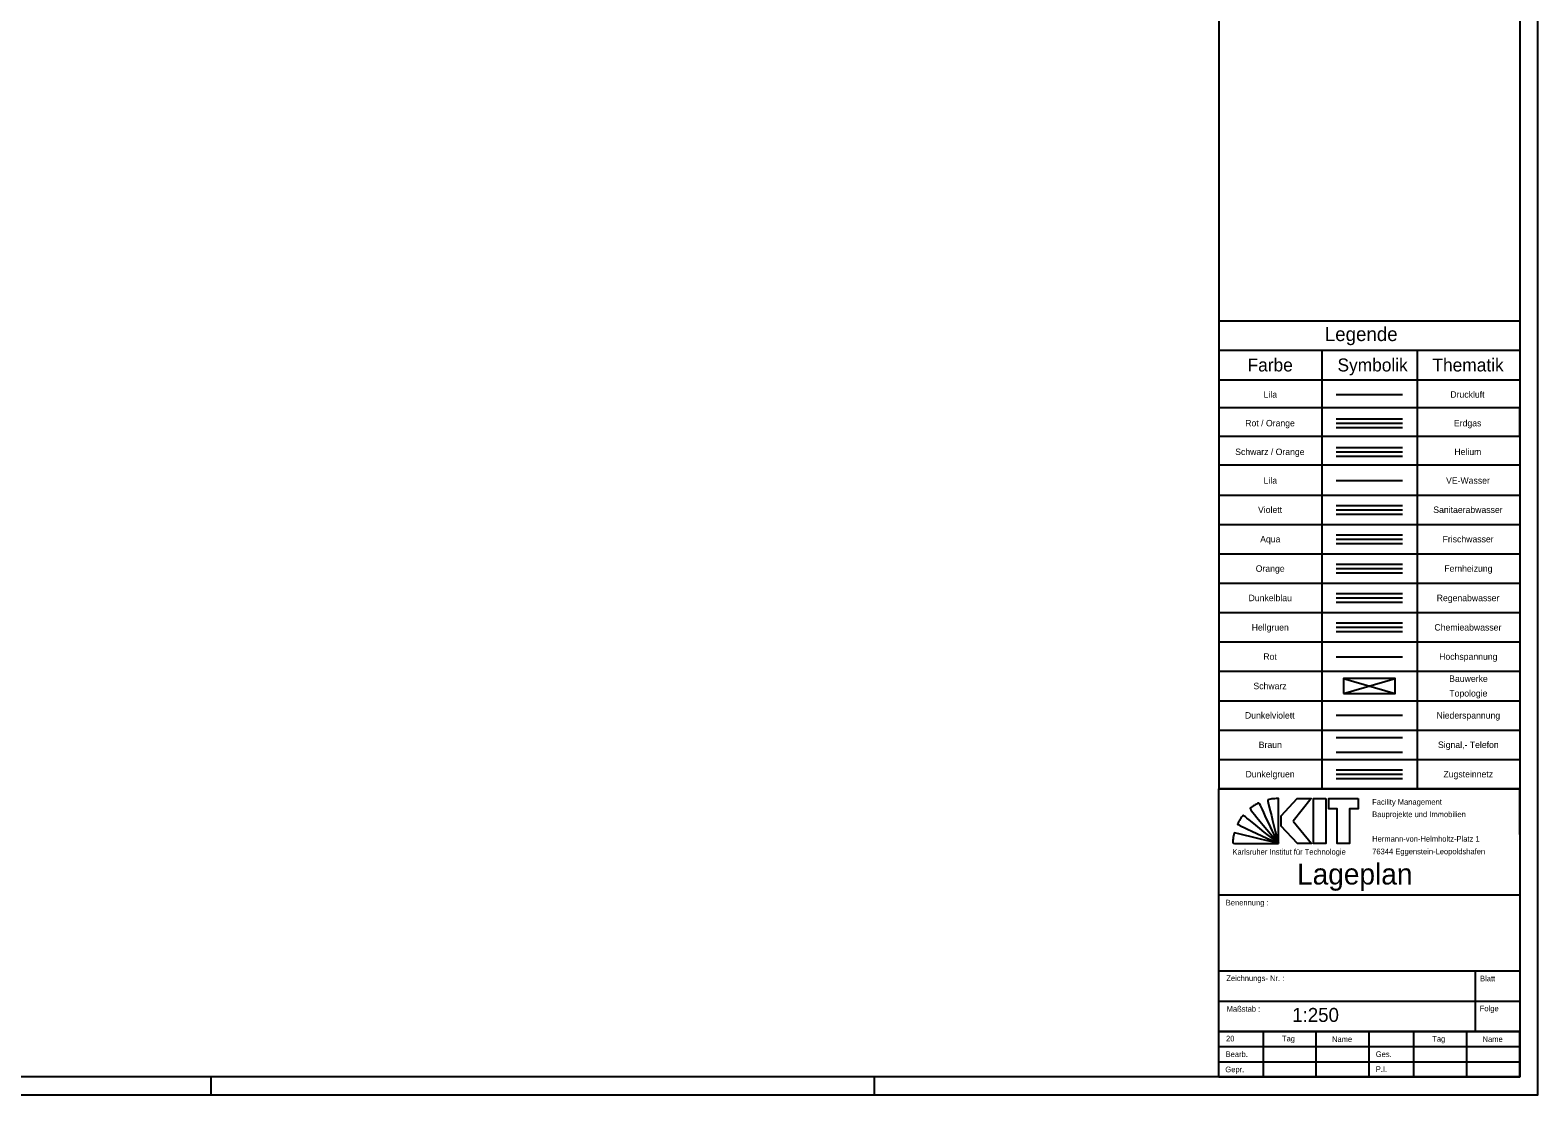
# Model space of a CAD drawing. Extents: x -36550144 to -36549934, y 4853173 to 4853322.
# Drawn here: x -36550038.7 to -36549933.6, y 4853173.1 to 4853247.4 of the extents above; entities that cross this region are included whole.
import ezdxf

# ---------------------------------------------------------------- set-up
doc = ezdxf.new("R2010")
doc.units = 0
doc.layers.add('Ebene 1', color=7, linetype='Continuous')

msp = doc.modelspace()

# ---------------------------------------------------------------- linework, layer by layer
at = {"layer": 'Ebene 1'}
for p, q in [((-36549934.81, 4853320.36), (-36549934.81, 4853219.03)), ((-36549955.81, 4853227.08), (-36549934.81, 4853227.08)), ((-36549934.81, 4853225.03), (-36549955.81, 4853225.03)), ((-36549948.63, 4853225.03), (-36549948.63, 4853194.46)), ((-36549941.98, 4853225.03), (-36549941.98, 4853194.46)), ((-36549955.81, 4853222.98), (-36549934.81, 4853222.98)), ((-36549947.61, 4853221.96), (-36549943, 4853221.96)), ((-36549934.81, 4853221.03), (-36549955.81, 4853221.03)), ((-36549934.81, 4853219.03), (-36549934.81, 4853221.08)), ((-36549947.61, 4853219.96), (-36549943, 4853219.96)), ((-36549934.81, 4853219.03), (-36549955.81, 4853219.03)), ((-36549934.81, 4853219.03), (-36549934.81, 4853194.46)), ((-36549947.61, 4853217.96), (-36549943, 4853217.96)), ((-36549934.81, 4853217.03), (-36549955.81, 4853217.03)), ((-36549947.61, 4853215.96), (-36549943, 4853215.96)), ((-36549955.81, 4853214.94), (-36549934.81, 4853214.94)), ((-36549955.81, 4853212.89), (-36549934.81, 4853212.89)), ((-36549955.81, 4853210.84), (-36549934.81, 4853210.84)), ((-36549955.81, 4853208.79), (-36549934.81, 4853208.79)), ((-36549955.81, 4853206.74), (-36549934.81, 4853206.74)), ((-36549955.81, 4853204.7), (-36549934.81, 4853204.7)), ((-36549947.61, 4853203.67), (-36549943, 4853203.67)), ((-36549955.81, 4853202.65), (-36549934.81, 4853202.65)), ((-36549947.1, 4853201.11), (-36549943.51, 4853202.14)), ((-36549947.1, 4853202.14), (-36549943.51, 4853201.11)), ((-36549955.81, 4853200.6), (-36549934.81, 4853200.6)), ((-36549947.61, 4853199.58), (-36549943, 4853199.58)), ((-36549955.81, 4853198.55), (-36549934.81, 4853198.55)), ((-36549947.61, 4853198.04), (-36549943, 4853198.04)), ((-36549947.61, 4853197.02), (-36549943, 4853197.02)), ((-36549955.81, 4853196.5), (-36549934.81, 4853196.5)), ((-36549955.81, 4853191.28), (-36549955.81, 4853194.46)), ((-36549955.81, 4853194.46), (-36549934.81, 4853194.46)), ((-36549934.81, 4853194.46), (-36549955.8, 4853194.46)), ((-36549934.81, 4853191.28), (-36549934.81, 4853194.46)), ((-36549934.81, 4853191.28), (-36549934.81, 4853177.54)), ((-36549934.81, 4853191.28), (-36549934.81, 4853177.54)), ((-36549955.81, 4853187.05), (-36549934.81, 4853187.05)), ((-36549955.81, 4853181.77), (-36549934.81, 4853181.77)), ((-36549937.9, 4853177.54), (-36549937.9, 4853181.77)), ((-36549955.81, 4853179.65), (-36549934.81, 4853179.65)), ((-36549955.81, 4853177.54), (-36549934.81, 4853177.54)), ((-36549955.81, 4853177.54), (-36549934.81, 4853177.54)), ((-36549955.81, 4853177.54), (-36549934.81, 4853177.54)), ((-36549955.81, 4853177.54), (-36549934.81, 4853177.54)), ((-36549955.81, 4853174.36), (-36549955.81, 4853177.54)), ((-36549952.72, 4853177.54), (-36549952.72, 4853174.36)), ((-36549949.01, 4853174.36), (-36549949.01, 4853177.54)), ((-36549942.22, 4853177.54), (-36549942.22, 4853174.36)), ((-36549938.51, 4853174.36), (-36549938.51, 4853177.54)), ((-36549934.81, 4853174.36), (-36549934.81, 4853177.54)), ((-36549955.81, 4853176.48), (-36549945.31, 4853176.48)), ((-36549945.31, 4853176.48), (-36549934.81, 4853176.48)), ((-36549945.31, 4853174.36), (-36549945.31, 4853176.48)), ((-36549955.81, 4853175.42), (-36549945.31, 4853175.42)), ((-36549945.31, 4853175.42), (-36549934.81, 4853175.42)), ((-36550026.06, 4853173.11), (-36550026.06, 4853174.36)), ((-36549979.81, 4853173.11), (-36549979.81, 4853174.36)), ((-36549955.81, 4853174.36), (-36549934.81, 4853174.36)), ((-36549955.81, 4853174.36), (-36549934.81, 4853174.36)), ((-36549945.31, 4853174.36), (-36549945.31, 4853174.36))]:
    msp.add_line(p, q, dxfattribs=at)
for points in [[(-36550143.81, 4853173.11), (-36549933.56, 4853173.11), (-36549933.56, 4853321.61), (-36550143.81, 4853321.61)], [(-36550137.56, 4853320.36), (-36549934.81, 4853320.36), (-36549934.81, 4853174.36), (-36550137.56, 4853174.36)], [(-36549947.1, 4853201.11), (-36549943.51, 4853201.11), (-36549943.51, 4853202.14), (-36549947.1, 4853202.14)]]:
    msp.add_lwpolyline(points, close=True, dxfattribs=at)
for points in [[(-36549934.81, 4853320.36), (-36549955.81, 4853320.36), (-36549955.81, 4853194.46)], [(-36549947.61, 4853220.26), (-36549943, 4853220.26)], [(-36549947.61, 4853219.66), (-36549943, 4853219.66)], [(-36549947.61, 4853218.26), (-36549943, 4853218.26)], [(-36549947.61, 4853217.66), (-36549943, 4853217.66)], [(-36549947.61, 4853214.21), (-36549943, 4853214.21)], [(-36549947.61, 4853213.91), (-36549943, 4853213.91)], [(-36549947.61, 4853213.61), (-36549943, 4853213.61)], [(-36549947.61, 4853212.17), (-36549943, 4853212.17)], [(-36549947.61, 4853211.86), (-36549943, 4853211.86)], [(-36549947.61, 4853211.56), (-36549943, 4853211.56)], [(-36549947.61, 4853210.12), (-36549943, 4853210.12)], [(-36549947.61, 4853209.82), (-36549943, 4853209.82)], [(-36549947.61, 4853209.52), (-36549943, 4853209.52)], [(-36549947.61, 4853208.07), (-36549943, 4853208.07)], [(-36549947.61, 4853207.77), (-36549943, 4853207.77)], [(-36549947.61, 4853207.47), (-36549943, 4853207.47)], [(-36549947.61, 4853206.02), (-36549943, 4853206.02)], [(-36549947.61, 4853205.72), (-36549943, 4853205.72)], [(-36549947.61, 4853205.42), (-36549943, 4853205.42)], [(-36549947.61, 4853195.78), (-36549943, 4853195.78)], [(-36549947.61, 4853195.48), (-36549943, 4853195.48)], [(-36549947.61, 4853195.18), (-36549943, 4853195.18)], [(-36549950.63, 4853192.19), (-36549949.35, 4853190.64), (-36549950.31, 4853190.64), (-36549951.45, 4853191.86), (-36549951.45, 4853192.56), (-36549950.35, 4853193.77), (-36549949.36, 4853193.77), (-36549950.63, 4853192.19)], [(-36549948.35, 4853193.77), (-36549948.35, 4853190.64), (-36549949.21, 4853190.64), (-36549949.21, 4853193.77), (-36549948.35, 4853193.77)], [(-36549946.08, 4853193.77), (-36549946.08, 4853193.06), (-36549946.68, 4853193.06), (-36549946.68, 4853190.63), (-36549947.54, 4853190.63), (-36549947.54, 4853193.06), (-36549948.14, 4853193.06), (-36549948.14, 4853193.77), (-36549946.08, 4853193.77)], [(-36549955.81, 4853177.54), (-36549955.81, 4853191.28)], [(-36549934.81, 4853177.54), (-36549955.81, 4853177.54)], [(-36549955.81, 4853177.54), (-36549955.81, 4853177.54)], [(-36549945.31, 4853174.36), (-36549945.31, 4853177.54)], [(-36549934.81, 4853174.36), (-36549934.81, 4853176.48)], [(-36549955.81, 4853174.36), (-36549934.81, 4853174.36)], [(-36549945.31, 4853174.36), (-36549934.81, 4853174.36)]]:
    msp.add_lwpolyline(points, dxfattribs=at)
for points in [[(-36549951.65, 4853190.64), (-36549951.65, 4853190.64), (-36549953.64, 4853193.07), (-36549953.64, 4853193.07), (-36549953.44, 4853193.23), (-36549953.22, 4853193.37), (-36549952.99, 4853193.48), (-36549952.99, 4853193.48), (-36549951.65, 4853190.64), (-36549951.65, 4853190.64), (-36549951.65, 4853190.64), (-36549951.65, 4853190.64), (-36549951.65, 4853190.64)], [(-36549951.65, 4853190.64), (-36549951.65, 4853190.64), (-36549952.41, 4853193.68), (-36549952.41, 4853193.68), (-36549952.18, 4853193.74), (-36549951.93, 4853193.77), (-36549951.67, 4853193.77), (-36549951.66, 4853193.77), (-36549951.66, 4853193.77), (-36549951.65, 4853193.77), (-36549951.65, 4853193.77), (-36549951.65, 4853190.64), (-36549951.65, 4853190.64), (-36549951.65, 4853190.64), (-36549951.65, 4853190.64), (-36549951.65, 4853190.64)], [(-36549951.65, 4853190.64), (-36549951.65, 4853190.64), (-36549954.51, 4853191.97), (-36549954.51, 4853191.97), (-36549954.41, 4853192.2), (-36549954.26, 4853192.42), (-36549954.1, 4853192.62), (-36549954.1, 4853192.62), (-36549951.65, 4853190.64), (-36549951.65, 4853190.64)], [(-36549951.65, 4853190.64), (-36549951.65, 4853190.64), (-36549954.82, 4853190.64), (-36549954.82, 4853190.64), (-36549954.82, 4853190.9), (-36549954.79, 4853191.16), (-36549954.72, 4853191.4), (-36549954.72, 4853191.4), (-36549951.65, 4853190.64), (-36549951.65, 4853190.64)]]:
    msp.add_open_spline(points, degree=3, dxfattribs=at)

# ---------------------------------------------------------------- texts
for s, height, p in [('Legende', 0.975, (-36549948.41, 4853225.68)), ('Farbe', 0.904, (-36549953.8, 4853223.56)), ('Symbolik', 0.904, (-36549947.53, 4853223.56)), ('Thematik', 0.904, (-36549940.91, 4853223.56)), ('Lila', 0.452, (-36549952.68, 4853221.73)), ('Druckluft', 0.452, (-36549939.66, 4853221.73)), ('Rot / Orange', 0.4518, (-36549953.96, 4853219.73)), ('Erdgas', 0.452, (-36549939.41, 4853219.73)), ('Schwarz / Orange', 0.4518, (-36549954.66, 4853217.73)), ('Helium', 0.452, (-36549939.38, 4853217.73)), ('Lila', 0.452, (-36549952.68, 4853215.73)), ('VE-Wasser', 0.452, (-36549939.96, 4853215.73)), ('Violett', 0.452, (-36549953.07, 4853213.69)), ('Sanitaerabwasser', 0.4518, (-36549940.85, 4853213.69)), ('Aqua', 0.452, (-36549952.92, 4853211.64)), ('Frischwasser', 0.4518, (-36549940.2, 4853211.64)), ('Orange', 0.452, (-36549953.23, 4853209.59)), ('Fernheizung', 0.4518, (-36549940.08, 4853209.59)), ('Dunkelblau', 0.452, (-36549953.73, 4853207.54)), ('Regenabwasser', 0.4518, (-36549940.61, 4853207.54)), ('Hellgruen', 0.452, (-36549953.51, 4853205.49)), ('Chemieabwasser', 0.4518, (-36549940.77, 4853205.49)), ('Hochspannung', 0.4518, (-36549940.44, 4853203.45)), ('Rot', 0.452, (-36549952.7, 4853203.45)), ('Schwarz', 0.452, (-36549953.39, 4853201.4)), ('Bauwerke', 0.452, (-36549939.74, 4853201.91)), ('Topologie', 0.452, (-36549939.73, 4853200.89)), ('Dunkelviolett', 0.4518, (-36549953.98, 4853199.35)), ('Niederspannung', 0.4518, (-36549940.62, 4853199.35)), ('Braun', 0.452, (-36549953.02, 4853197.3)), ('Signal,- Telefon', 0.4518, (-36549940.52, 4853197.3)), ('Dunkelgruen', 0.4518, (-36549953.94, 4853195.25)), ('Zugsteinnetz', 0.4518, (-36549940.14, 4853195.25)), ('Facility Management', 0.3938, (-36549945.11, 4853193.34)), ('Bauprojekte und Immobilien', 0.3938, (-36549945.11, 4853192.48)), ('Karlsruher Institut für Technologie', 0.3938, (-36549954.85, 4853189.86)), ('76344 Eggenstein-Leopoldshafen', 0.3938, (-36549945.11, 4853189.89)), ('Hermann-von-Helmholtz-Platz 1', 0.3938, (-36549945.11, 4853190.77)), ('Lageplan', 1.463, (-36549950.35, 4853187.78)), ('Benennung :', 0.3938, (-36549955.32, 4853186.32)), ('Zeichnungs- Nr. :', 0.3938, (-36549955.28, 4853181.05)), ('Blatt', 0.394, (-36549937.59, 4853181.03)), ('Maßstab :', 0.394, (-36549955.26, 4853178.91)), ('1:250     ', 0.975, (-36549950.69, 4853178.2)), ('Folge', 0.394, (-36549937.61, 4853178.94)), ('20', 0.394, (-36549955.3, 4853176.84)), ('Tag', 0.394, (-36549951.4, 4853176.84)), ('Name', 0.394, (-36549947.91, 4853176.8)), ('Tag', 0.394, (-36549940.92, 4853176.82)), ('Name', 0.394, (-36549937.41, 4853176.8)), ('Bearb.', 0.394, (-36549955.33, 4853175.75)), ('Ges.', 0.394, (-36549944.86, 4853175.75)), ('Gepr.', 0.394, (-36549955.35, 4853174.69)), ('P.I.', 0.394, (-36549944.86, 4853174.71))]:
    msp.add_text(s, height=height, dxfattribs=at).set_placement(p)

doc.saveas('drawing.dxf')
